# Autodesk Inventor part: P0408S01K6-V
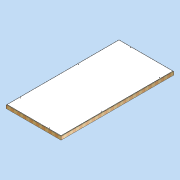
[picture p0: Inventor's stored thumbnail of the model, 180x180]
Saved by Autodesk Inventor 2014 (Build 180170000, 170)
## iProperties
Created: 2011-04
Part Number: P0408S01K6-V
Document SubType Name: Modeling
Designer: david.appleford
Density: 0.179099 g/cm^3
Description: 1w x 2w  01 Panel - 6 Locks
Cost Center: £128.00
Mass: 39000 g
Surface Area: 60298.9 cm^2
Volume: 217756 cm^3
Material: Generic
Appearance: Wood (Pine)
Justset: False
Title: 1w x 2w  01 Panel - 6 Locks
Author: david.appleford
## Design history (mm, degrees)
sketch "Sketch1"
  geometry: L1 (0, 0)-(1220, 0); L2 (1220, 0)-(1220, 2440); L3 (1220, 2440)-(0, 2440); L4 (0, 2440)-(0, 0); L5 (34, 2406)-(1186, 2406); L6 (1186, 2406)-(1186, 34); L7 (1186, 34)-(34, 34); L8 (34, 34)-(34, 2406)
  constraints: 16 end point, 4 parallel, 2 perpendicular, 1 horizontal, 3 other
  dimensions: "d0" = 1220 distance between parallel lines of L2 L4 (= w); "d1" = 2440 distance between parallel lines of L1 L3 (= 2 x w); "d2" = 34 distance between parallel lines of L5 L3 (= 0.5 x t)
extrude "Extrusion1" new body sketch "Sketch1" distance "d3" = 68 (= t); taper "d4" = 0 deg
sketch "Sketch2"
  geometry: L1 (1186, 2406)-(1186, 34) reference; L2 (34, 2406)-(1186, 2406) reference; L3 (34, 34)-(34, 2406) reference; L4 (1186, 34)-(34, 34) reference; L5 (1176, 2396)-(1176, 44); L6 (1176, 44)-(44, 44); L7 (44, 44)-(44, 2396); L8 (44, 2396)-(1176, 2396); 1 further point
  constraints: 8 end point, 3 other
  dimensions: "d5" = 10 distance between parallel lines of L8 L2
extrude "Extrusion2" join sketch "Sketch2" distance "d6" = 6 (= sw); taper "d7" = 0 deg
sketch "Sketch3"
  geometry: L1 (-44, 2396)-(-1176, 2396) reference; L2 (-1176, 2396)-(-1176, 44) reference; L3 (-44, 44)-(-44, 2396) reference; L4 (-1176, 44)-(-44, 44) reference; 1 further point
extrude "Extrusion3" join sketch "Sketch3" distance "d8" = 6 (= sw); taper "d9" = 0 deg
sketch "Sketch4"
  geometry: L1 (34, 2406)-(1186, 2406) reference; L2 (1186, 2406)-(1186, 34) reference; L3 (1186, 34)-(34, 34) reference; L4 (34, 34)-(34, 2406) reference; 7 further points
  constraints: 2 vertical alignment
  dimensions: "d10" = 28 distance from line of point (305, 2378) L1 (= k); "d12" = 28 distance from line of L3 point (915, 62) (= k); "d13" = 28 distance from line of point (62, 305) L4 (= k); "d14" = 305 horizontal distance of point (305, 2378) point (0, 0) (= 0.25 x w); "d15" = 610 horizontal distance of point (915, 62) point (305, 2378) (= 0.5 x w); "d16" = 305 vertical distance of point (62, 305) point (0, 0) (= 0.25 x w); "d17" = 1220 distance of point (62, 305) point (62, 1525) (= w); "d19" = 610 vertical distance of point (1158, 915) point (62, 305) (= 0.5 x w); "d20" = 1220 distance of point (1158, 915) point (1158, 2135) (= w)
hole "Hole1" sketch "Sketch4" at (305, 2378), (62, 1525), (62, 305), (1158, 2135), (1158, 915), (915, 62) diameter "d22" = 12 (= hd); stored, may be unused: countersink angle "d26" = 90 deg, drill point angle "d28" = 118 deg; dims "d23" = 6, "d24" = 4, "d25" = 2, "d27" = 8
body "Solid1"
node "Projected Loop1"
other parameters: "w" = 1220 [user parameter; used in 8 equation terms], "t" = 68 [user parameter; used in 2 equation terms], "e" = 16 [user parameter], "sw" = 6 [user parameter; used in 2 equation terms], "sc" = 9 [user parameter], "sf" = 12 [user parameter], "k" = 28 [user parameter; used in 3 equation terms], "hd" = 12 [user parameter; used in 1 equation term]
